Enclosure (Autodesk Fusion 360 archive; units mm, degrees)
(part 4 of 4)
sketch "Sketch57" plane through (0, 0, 0) normal (0, 0, -1) x axis (1, 0, 0)
  line L1 (10, -322.58) -> (10, -25)
  line L2 (232.58, -337.58) -> (25, -337.58)
  line L3 (247.58, -25) -> (247.58, -322.58)
  line L4 (25, -10) -> (232.58, -10)
  line L5 (103.7748, -244.2781) -> (91.8964, -251.7084)
  line L6 (108.0018, -231.1432) -> (108.0018, -236.648)
  line L7 (94.9373, -218.4422) -> (104.1813, -224.2382)
  line L8 (79.1901, -174.7773) -> (91.3374, -213.7689)
  line L9 (220.4778, -140.1755) -> (203.5713, -117.753)
  curve K1 (217.8042, -176.4831) -> (220.4778, -140.1755)
  line L10 (234.7917, -277.58) -> (234.7917, -212.7928)
  line L11 (94.639, -289.58) -> (222.7917, -289.58)
  line L12 (88.139, -258.4907) -> (88.139, -283.08)
  line L13 (158.8675, -75.8822) -> (158.8675, -124.8822)
  line L14 (102.3675, -68.3822) -> (151.3675, -68.3822)
  line L15 (94.8675, -124.8822) -> (94.8675, -75.8822)
  line L16 (151.3675, -132.3822) -> (102.3675, -132.3822)
  line L17 (184.5018, -268.1648) -> (135.5018, -268.1648)
  line L18 (192.0018, -211.6648) -> (192.0018, -260.6648)
  line L19 (135.5018, -204.1648) -> (184.5018, -204.1648)
  line L20 (128.0018, -260.6648) -> (128.0018, -211.6648)
  arc A1 centre (25, -25) radius 15 clockwise from (10, -25) to (25, -10)
  arc A2 centre (25, -322.58) radius 15 clockwise from (25, -337.58) to (10, -322.58)
  arc A3 centre (232.58, -322.58) radius 15 clockwise from (247.58, -322.58) to (232.58, -337.58)
  arc A4 centre (232.58, -25) radius 15 clockwise from (232.58, -10) to (247.58, -25)
  arc A5 centre (96.139, -258.4907) radius 8 clockwise from (88.139, -258.4907) to (91.8964, -251.7084)
  arc A6 centre (99.0018, -236.648) radius 9 clockwise from (108.0018, -236.648) to (103.7748, -244.2781)
  arc A7 centre (99.8518, -231.1432) radius 8.15 clockwise from (104.1813, -224.2382) to (108.0018, -231.1432)
  arc A8 centre (99.4527, -211.2407) radius 8.5 clockwise from (94.9373, -218.4422) to (91.3374, -213.7689)
  arc A9 centre (127.0824, -115.0779) radius 76.5356 clockwise from (79.1901, -174.7773) to (203.5713, -117.753)
  arc A10 centre (225.6505, -186.2784) radius 12.5504 clockwise from (223.1642, -198.5801) to (217.8042, -176.4831)
  arc A11 centre (220.2917, -212.7928) radius 14.5 clockwise from (223.1642, -198.5801) to (234.7917, -212.7928)
  arc A12 centre (222.7917, -277.58) radius 12 clockwise from (234.7917, -277.58) to (222.7917, -289.58)
  arc A13 centre (94.639, -283.08) radius 6.5 clockwise from (94.639, -289.58) to (88.139, -283.08)
  circle C1 centre (96.79, -233.79) radius 3
  circle C2 centre (88.5825, -41.4103) radius 4
  circle C3 centre (224.492, -186.2784) radius 3
  circle C4 centre (232.58, -322.58) radius 3
  circle C5 centre (237.58, -173.79) radius 3
  circle C6 centre (25, -25) radius 3
  circle C7 centre (25, -322.58) radius 3
  circle C8 centre (232.58, -25) radius 3
  circle C9 centre (20, -173.79) radius 3
  circle C10 centre (100.9647, -87.9081) radius 1.375
  circle C11 centre (100.9647, -112.8564) radius 1.375
  circle C12 centre (106.9491, -88.8821) radius 1.5
  circle C13 centre (154.3403, -108.8564) radius 1.375
  circle C14 centre (106.9489, -111.8821) radius 1.5
  circle C15 centre (119.001, -121.9951) radius 1.5
  circle C16 centre (150.622, -84.1868) radius 1.375
  circle C17 centre (112.0836, -82.7631) radius 1.5
  circle C18 centre (137.3711, -127.1448) radius 1.375
  circle C19 centre (149.5182, -96.3884) radius 1.5
  circle C20 centre (104.217, -104.376) radius 1.5
  circle C21 centre (105.7923, -80.8273) radius 1.375
  circle C22 centre (146.7861, -111.8823) radius 1.5
  circle C23 centre (129.0161, -129.0518) radius 1.375
  circle C24 centre (142.1417, -92.3657) radius 1.625
  circle C25 centre (137.3711, -73.6196) radius 1.375
  circle C26 centre (105.7923, -119.9372) radius 1.375
  circle C27 centre (98.4387, -96.0973) radius 1.375
  circle C28 centre (120.4701, -72.353) radius 1.375
  circle C29 centre (122.2157, -103.762) radius 1.875
  circle C30 centre (136.6667, -114.5787) radius 1.625
  circle C31 centre (128.6444, -94.9136) radius 1.875
  circle C32 centre (134.2595, -109.1918) radius 1.75
  circle C33 centre (144.1176, -100.3822) radius 1.625
  circle C34 centre (142.1417, -108.3987) radius 1.625
  circle C35 centre (120.7507, -84.2532) radius 1.625
  circle C36 centre (126.8676, -100.3822) radius 2
  circle C37 centre (120.7507, -116.5113) radius 1.625
  circle C38 centre (113.9558, -111.8211) radius 1.625
  circle C39 centre (116.9084, -94.6321) radius 1.75
  circle C40 centre (128.9468, -117.5065) radius 1.625
  circle C41 centre (126.8675, -111.8822) radius 1.75
  circle C42 centre (132.6176, -100.3822) radius 1.875
  circle C43 centre (115.5423, -102.379) radius 1.75
  circle C44 centre (130.8009, -89.5758) radius 1.75
  circle C45 centre (113.9558, -88.9434) radius 1.625
  circle C46 centre (155.6176, -100.3822) radius 1.375
  arc A14 centre (151.3675, -124.8822) radius 7.5 clockwise from (158.8675, -124.8822) to (151.3675, -132.3822)
  arc A15 centre (151.3675, -75.8822) radius 7.5 clockwise from (151.3675, -68.3822) to (158.8675, -75.8822)
  arc A16 centre (102.3675, -75.8822) radius 7.5 clockwise from (94.8675, -75.8822) to (102.3675, -68.3822)
  arc A17 centre (102.3675, -124.8822) radius 7.5 clockwise from (102.3675, -132.3822) to (94.8675, -124.8822)
  circle C47 centre (136.8269, -94.6323) radius 1.75
  circle C48 centre (138.1929, -102.3793) radius 1.75
  circle C49 centre (128.6444, -105.8508) radius 1.875
  circle C50 centre (119.4754, -109.1916) radius 1.75
  circle C51 centre (122.2157, -97.0025) radius 1.875
  circle C52 centre (136.6667, -86.1858) radius 1.625
  circle C53 centre (110.1188, -104.5104) radius 1.625
  circle C54 centre (128.9468, -83.258) radius 1.625
  circle C55 centre (122.9345, -89.5757) radius 1.75
  circle C56 centre (126.8675, -123.3822) radius 1.5
  circle C57 centre (110.1188, -96.254) radius 1.625
  circle C58 centre (144.7929, -122.8599) radius 1.375
  circle C59 centre (146.7862, -88.8823) radius 1.5
  circle C60 centre (126.8677, -77.3822) radius 1.5
  circle C61 centre (129.0161, -71.7126) radius 1.375
  circle C62 centre (144.7929, -77.9046) radius 1.375
  circle C63 centre (120.4701, -128.4114) radius 1.375
  circle C64 centre (154.3403, -91.908) radius 1.375
  circle C65 centre (134.7342, -78.7693) radius 1.5
  circle C66 centre (150.622, -116.5777) radius 1.375
  circle C67 centre (141.6518, -82.7633) radius 1.5
  circle C68 centre (149.5181, -104.3763) radius 1.5
  circle C69 centre (119.0012, -78.7692) radius 1.5
  circle C70 centre (112.4926, -75.484) radius 1.375
  circle C71 centre (141.6516, -118.0013) radius 1.5
  circle C72 centre (112.4926, -125.2805) radius 1.375
  circle C73 centre (104.217, -96.3882) radius 1.5
  circle C74 centre (134.7339, -121.9952) radius 1.5
  circle C75 centre (98.4387, -104.6672) radius 1.375
  circle C76 centre (112.0834, -118.0012) radius 1.5
  circle C77 centre (172.476, -210.2621) radius 1.375
  circle C78 centre (147.5277, -210.2621) radius 1.375
  circle C79 centre (171.502, -216.2464) radius 1.5
  circle C80 centre (151.5276, -263.6376) radius 1.375
  circle C81 centre (148.502, -216.2463) radius 1.5
  circle C82 centre (138.389, -228.2983) radius 1.5
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offset_faces "OffsetFaces1" distance 0.75 (= "acr_kerf")
step "Arrange11" AngleFromX 0 Priority 500 AngleFromX 0 Priority 500 AngleFromX 0 Priority 500 originOffsetX 0 originOffsetY 0 envelopeLength 270 envelopeWidth 400 envelopeSpacing 0 grainDirection 0 objectSpacing 20 frameWidth 10 placementClearance 0
sketch "Sketch58" plane through (0, 0, 2) normal (0, 0, 1) x axis (-1, 0, 0)
  line L1 (-10, -25.75) -> (-10, -323.33)
  line L2 (-233.33, -10) -> (-25.75, -10)
  line L3 (-249.08, -323.33) -> (-249.08, -25.75)
  line L4 (-25.75, -339.08) -> (-233.33, -339.08)
  line L5 (-104.5248, -104.0519) -> (-92.6464, -96.6216)
  line L6 (-108.7518, -117.1868) -> (-108.7518, -111.682)
  line L7 (-95.6873, -129.8877) -> (-104.9313, -124.0918)
  line L8 (-79.9401, -173.5527) -> (-92.0874, -134.561)
  line L9 (-221.2278, -208.1545) -> (-204.3213, -230.577)
  curve K1 (-218.5542, -171.8469) -> (-221.2278, -208.1545)
  line L10 (-235.5417, -70.75) -> (-235.5417, -135.5372)
  line L11 (-95.389, -58.75) -> (-223.5417, -58.75)
  line L12 (-88.889, -89.8392) -> (-88.889, -65.25)
  line L13 (-166.8314, -268.6862) -> (-166.8314, -219.6862)
  line L14 (-109.5814, -276.9362) -> (-158.5814, -276.9362)
  line L15 (-101.3314, -219.6862) -> (-101.3314, -268.6862)
  line L16 (-158.5814, -211.4362) -> (-109.5814, -211.4362)
  line L17 (-137.0019, -145.905) -> (-186.0019, -145.905)
  line L18 (-128.7519, -88.655) -> (-128.7519, -137.655)
  line L19 (-186.0019, -80.405) -> (-137.0019, -80.405)
  line L20 (-194.2519, -137.655) -> (-194.2519, -88.655)
  arc A1 centre (-25.75, -323.33) radius 15.75 clockwise from (-10, -323.33) to (-25.75, -339.08)
  arc A2 centre (-25.75, -25.75) radius 15.75 clockwise from (-25.75, -10) to (-10, -25.75)
  arc A3 centre (-233.33, -25.75) radius 15.75 clockwise from (-249.08, -25.75) to (-233.33, -10)
  arc A4 centre (-233.33, -323.33) radius 15.75 clockwise from (-233.33, -339.08) to (-249.08, -323.33)
  arc A5 centre (-96.889, -89.8392) radius 8 clockwise from (-88.889, -89.8392) to (-92.6464, -96.6216)
  arc A6 centre (-99.7518, -111.682) radius 9 clockwise from (-108.7518, -111.682) to (-104.5248, -104.0519)
  arc A7 centre (-100.6018, -117.1868) radius 8.15 clockwise from (-104.9313, -124.0918) to (-108.7518, -117.1868)
  arc A8 centre (-100.2027, -137.0892) radius 8.5 clockwise from (-95.6873, -129.8877) to (-92.0874, -134.561)
  arc A9 centre (-127.8324, -233.2521) radius 76.5356 clockwise from (-79.9401, -173.5527) to (-204.3213, -230.577)
  arc A10 centre (-226.4005, -162.0515) radius 12.5504 clockwise from (-223.9142, -149.7498) to (-218.5542, -171.8469)
  arc A11 centre (-221.0417, -135.5372) radius 14.5 clockwise from (-223.9142, -149.7498) to (-235.5417, -135.5372)
  arc A12 centre (-223.5417, -70.75) radius 12 clockwise from (-235.5417, -70.75) to (-223.5417, -58.75)
  arc A13 centre (-95.389, -65.25) radius 6.5 clockwise from (-95.389, -58.75) to (-88.889, -65.25)
  circle C1 centre (-97.54, -114.54) radius 3
  circle C2 centre (-89.3325, -306.9197) radius 4
  circle C3 centre (-225.242, -162.0515) radius 3
  circle C4 centre (-233.33, -25.75) radius 3
  circle C5 centre (-238.33, -174.54) radius 3
  circle C6 centre (-25.75, -323.33) radius 3
  circle C7 centre (-25.75, -25.75) radius 3
  circle C8 centre (-233.33, -323.33) radius 3
  circle C9 centre (-20.75, -174.54) radius 3
  circle C10 centre (-121.6072, -270.0889) radius 1.375
  circle C11 centre (-146.5555, -270.0889) radius 1.375
  circle C12 centre (-122.5812, -264.1046) radius 1.5
  circle C13 centre (-142.5556, -216.7133) radius 1.375
  circle C14 centre (-145.5812, -264.1047) radius 1.5
  circle C15 centre (-155.6942, -252.0527) radius 1.5
  circle C16 centre (-117.8859, -220.4317) radius 1.375
  circle C17 centre (-116.4622, -258.9701) radius 1.5
  circle C18 centre (-160.844, -233.6825) radius 1.375
  circle C19 centre (-130.0876, -221.5355) radius 1.5
  circle C20 centre (-138.0751, -266.8367) radius 1.5
  circle C21 centre (-114.5264, -265.2613) radius 1.375
  circle C22 centre (-145.5815, -224.2675) radius 1.5
  circle C23 centre (-162.751, -242.0376) radius 1.375
  circle C24 centre (-126.0649, -228.9119) radius 1.625
  circle C25 centre (-107.3187, -233.6825) radius 1.375
  circle C26 centre (-153.6363, -265.2613) radius 1.375
  circle C27 centre (-129.7964, -272.6149) radius 1.375
  circle C28 centre (-106.0522, -250.5835) radius 1.375
  circle C29 centre (-137.4611, -248.8379) radius 1.875
  circle C30 centre (-148.2778, -234.3869) radius 1.625
  circle C31 centre (-128.6128, -242.4092) radius 1.875
  circle C32 centre (-142.8909, -236.7941) radius 1.75
  circle C33 centre (-134.0814, -226.9361) radius 1.625
  circle C34 centre (-142.0978, -228.9119) radius 1.625
  circle C35 centre (-117.9523, -250.303) radius 1.625
  circle C36 centre (-134.0814, -244.1861) radius 2
  circle C37 centre (-150.2104, -250.303) radius 1.625
  circle C38 centre (-145.5202, -257.0979) radius 1.625
  circle C39 centre (-128.3312, -254.1453) radius 1.75
  circle C40 centre (-151.2056, -242.1068) radius 1.625
  circle C41 centre (-145.5814, -244.1862) radius 1.75
  circle C42 centre (-134.0814, -238.4361) radius 1.875
  circle C43 centre (-136.0782, -255.5114) radius 1.75
  circle C44 centre (-123.2749, -240.2527) radius 1.75
  circle C45 centre (-122.6425, -257.0979) radius 1.625
  circle C46 centre (-134.0814, -215.4361) radius 1.375
  arc A14 centre (-158.5814, -219.6862) radius 8.25 clockwise from (-166.8314, -219.6862) to (-158.5814, -211.4362)
  arc A15 centre (-158.5814, -268.6862) radius 8.25 clockwise from (-158.5814, -276.9362) to (-166.8314, -268.6862)
  arc A16 centre (-109.5814, -268.6862) radius 8.25 clockwise from (-101.3314, -268.6862) to (-109.5814, -276.9362)
  arc A17 centre (-109.5814, -219.6862) radius 8.25 clockwise from (-109.5814, -211.4362) to (-101.3314, -219.6862)
  circle C47 centre (-128.3315, -234.2267) radius 1.75
  circle C48 centre (-136.0784, -232.8608) radius 1.75
  circle C49 centre (-139.5499, -242.4092) radius 1.875
  circle C50 centre (-142.8908, -251.5782) radius 1.75
  circle C51 centre (-130.7016, -248.8379) radius 1.875
  circle C52 centre (-119.8849, -234.3869) radius 1.625
  circle C53 centre (-138.2095, -260.9348) radius 1.625
  circle C54 centre (-116.9571, -242.1068) radius 1.625
  circle C55 centre (-123.2748, -248.1192) radius 1.75
  circle C56 centre (-157.0814, -244.1862) radius 1.5
  circle C57 centre (-129.9532, -260.9348) radius 1.625
  circle C58 centre (-156.559, -226.2607) radius 1.375
  circle C59 centre (-122.5815, -224.2674) radius 1.5
  circle C60 centre (-111.0814, -244.1859) radius 1.5
  circle C61 centre (-105.4117, -242.0376) radius 1.375
  circle C62 centre (-111.6037, -226.2607) radius 1.375
  circle C63 centre (-162.1105, -250.5835) radius 1.375
  circle C64 centre (-125.6071, -216.7133) radius 1.375
  circle C65 centre (-112.4685, -236.3195) radius 1.5
  circle C66 centre (-150.2768, -220.4317) radius 1.375
  circle C67 centre (-116.4624, -229.4018) radius 1.5
  circle C68 centre (-138.0754, -221.5355) radius 1.5
  circle C69 centre (-112.4684, -252.0524) radius 1.5
  circle C70 centre (-109.1831, -258.5611) radius 1.375
  circle C71 centre (-151.7005, -229.402) radius 1.5
  circle C72 centre (-158.9796, -258.5611) radius 1.375
  circle C73 centre (-130.0873, -266.8366) radius 1.5
  circle C74 centre (-155.6943, -236.3197) radius 1.5
  circle C75 centre (-138.3663, -272.6149) radius 1.375
  circle C76 centre (-151.7003, -258.9703) radius 1.5
  circle C77 centre (-135.5992, -100.6808) radius 1.375
  circle C78 centre (-135.5992, -125.6291) radius 1.375
  circle C79 centre (-141.5835, -101.6549) radius 1.5
  circle C80 centre (-188.9747, -121.6292) radius 1.375
  circle C81 centre (-141.5834, -124.6549) radius 1.5
  circle C82 centre (-153.6354, -134.7679) radius 1.5
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component_from_bodies "Body->Comp23"
component_from_bodies "Body->Comp24"
component_from_bodies "Body->Comp25"
offset_faces "OffsetFaces1" distance -2.5
sketch "Sketch59" plane through (0, -174.4464, 63.4933) normal (0, -0.9397, 0.342) x axis (1, 0, 0)
  line L1 (16, -22.9002) -> (16, 15.0998)
  line L2 (-45, -22.9002) -> (16, -22.9002)
  line L3 (-48, 12.0998) -> (-48, -19.9002)
  line L4 (16, 15.0998) -> (-45, 15.0998)
  line L5 (50, 12.0998) -> (50, -19.9002)
  line L6 (-45, 17.0998) -> (45, 17.0998)
  line L7 (-50, -19.9002) -> (-50, 12.0998)
  line L8 (45, -24.9002) -> (-45, -24.9002)
  arc A1 centre (-45, -19.9002) radius 3 clockwise from (-45, -22.9002) to (-48, -19.9002)
  arc A2 centre (-45, 12.0998) radius 3 clockwise from (-48, 12.0998) to (-45, 15.0998)
  arc A3 centre (45, -19.9002) radius 5 clockwise from (50, -19.9002) to (45, -24.9002)
  arc A4 centre (45, 12.0998) radius 5 clockwise from (45, 17.0998) to (50, 12.0998)
  arc A5 centre (-45, 12.0998) radius 5 clockwise from (-50, 12.0998) to (-45, 17.0998)
  arc A6 centre (-45, -19.9002) radius 5 clockwise from (-45, -24.9002) to (-50, -19.9002)
  circle C1 centre (31.25, -3.9002) radius 12.5
  circle C2 centre (31.25, -3.9002) radius 12.5
  circle C3 centre (31.25, -3.9002) radius 11.75
  dimension "d434" = -0.75
extrude "Extrude39" new body sketch "Sketch59" profile of C3 along normal blind 7.5 bodies "KNOB"
fillet "Fillet8" radius 2.5
sketch "Sketch60" plane through (0, -181.4941, 66.0584) normal (0, -0.9397, 0.342) x axis (1, 0, 0)
  circle C1 centre (31.25, -3.9002) radius 9.25
extrude "Extrude40" cut sketch "Sketch60" against normal blind 1
sketch "Sketch61" plane through (0, -180.5544, 65.7164) normal (0, -0.9397, 0.342) x axis (1, 0, 0)
  circle C1 centre (31.25, -3.9002) radius 9.25
  point P2 (31.25, -3.9002)
  point P3 (31.25, -3.9002)
  coincident P2 P3
loft "Loft1" sketch "Sketch60"
extrude "Extrude41" add of existing geometry blind 1
combine "Combine1"
sketch "Sketch62" plane through (0, -174.4464, 63.4933) normal (0, 0.9397, -0.342) x axis (-1, 0, 0)
  circle C1 centre (-31.25, -3.9002) radius 11.75
  circle C2 centre (-31.25, -3.9002) radius 2.8625
  concentric C1 C2
  dimension "d444" diameter C2 = 5.725
extrude "Extrude42" cut sketch "Sketch62" profile of C2 against normal blind 5
extrude "Extrude43" add of existing geometry blind 5
offset_faces "OffsetFaces1" bodies "L1_2"
offset_faces "OffsetFaces5"
component_from_bodies "Body->Comp26"
offset_faces "OffsetFaces1" distance -4
offset_faces "OffsetFaces2" distance 2.5
sketch "Sketch67" plane through (0, -174.4464, 63.4933) normal (0, -0.9397, 0.342) x axis (1, 0, 0)
  line L1 (-48, 12.0998) -> (-48, -19.9002)
  line L2 (16, 15.0998) -> (-45, 15.0998)
  line L3 (16, -22.9002) -> (16, 15.0998)
  line L4 (-45, -22.9002) -> (16, -22.9002)
  line L5 (-50, -19.9002) -> (-50, 12.0998)
  line L6 (45, -24.9002) -> (-45, -24.9002)
  line L7 (50, 12.0998) -> (50, -19.9002)
  line L8 (-45, 17.0998) -> (45, 17.0998)
  line L9 (31.25, -24.9002) -> (31.25, 17.0998)
  arc A1 centre (-45, 12.0998) radius 3 clockwise from (-48, 12.0998) to (-45, 15.0998)
  arc A2 centre (-45, -19.9002) radius 3 clockwise from (-45, -22.9002) to (-48, -19.9002)
  arc A3 centre (-45, -19.9002) radius 5 clockwise from (-45, -24.9002) to (-50, -19.9002)
  arc A4 centre (45, -19.9002) radius 5 clockwise from (50, -19.9002) to (45, -24.9002)
  arc A5 centre (45, 12.0998) radius 5 clockwise from (45, 17.0998) to (50, 12.0998)
  arc A6 centre (-45, 12.0998) radius 5 clockwise from (-50, 12.0998) to (-45, 17.0998)
  circle C1 centre (31.25, -3.9002) radius 12.5
  circle C2 centre (31.25, -3.9002) radius 12.5
  circle C3 centre (31.25, -2.4002) radius 12.5
  point P22 (31.25, 17.0998)
  point P23 (31.25, -24.9002)
  point P20 (31.25, -3.9002)
  point P24 (31.25, -2.4002)
  point P25 (31.25, -2.4002)
  coincident L8 P22
  coincident L6 P23
  perpendicular L6 L9
  coincident P20 L9
  coincident L9 P24
  coincident P24 P25
  dimension "d479" distance L6 P24 = 22.5 (= "16.5 mm + 6 mm")
  dimension "d480" diameter C3 = 25
extrude "Extrude1" add sketch "Sketch67" profile of C1 C2 C3 against normal blind 5
extrude "Extrude2" cut sketch "Sketch67" profile of C1 C2 C3 against normal blind 5
extrude "Extrude1" add of existing geometry blind 2
offset_faces "OffsetFaces2"
offset_faces "OffsetFaces3"
sketch "Sketch68" plane through (0, -174.4464, 63.4933) normal (0, -0.9397, 0.342) x axis (1, 0, 0)
  line L1 (-48, 12.0998) -> (-48, -19.9002)
  line L2 (16, 15.0998) -> (-45, 15.0998)
  line L3 (16, -22.9002) -> (16, 15.0998)
  line L4 (-45, -22.9002) -> (16, -22.9002)
  line L5 (-50, -19.9002) -> (-50, 12.0998)
  line L6 (45, -24.9002) -> (-45, -24.9002)
  line L7 (50, 12.0998) -> (50, -19.9002)
  line L8 (-45, 17.0998) -> (45, 17.0998)
  line L9 (16, -22.9002) -> (-45, -22.9002)
  line L10 (16, -21.4002) -> (16, -22.9002)
  line L11 (-41.5, -21.4002) -> (16, -21.4002)
  line L12 (-41.5, -13.9002) -> (-41.5, -21.4002)
  line L13 (-46.5, -10.4002) -> (-45, -10.4002)
  line L14 (-46.5, 2.5998) -> (-46.5, -10.4002)
  line L15 (-45, 2.5998) -> (-46.5, 2.5998)
  line L16 (-41.5, 13.5998) -> (-41.5, 6.0998)
  line L17 (16, 13.5998) -> (-41.5, 13.5998)
  line L18 (16, 15.0998) -> (16, 13.5998)
  line L19 (-45, 15.0998) -> (16, 15.0998)
  line L20 (-48, -19.9002) -> (-48, 12.0998)
  line L21 (16, -22.9002) -> (16, 15.0998)
  circle C1 centre (31.25, -2.4002) radius 12.5
  arc A1 centre (-45, 12.0998) radius 3 clockwise from (-48, 12.0998) to (-45, 15.0998)
  arc A2 centre (-45, -19.9002) radius 3 clockwise from (-45, -22.9002) to (-48, -19.9002)
  arc A3 centre (-45, -19.9002) radius 5 clockwise from (-45, -24.9002) to (-50, -19.9002)
  arc A4 centre (45, -19.9002) radius 5 clockwise from (50, -19.9002) to (45, -24.9002)
  arc A5 centre (45, 12.0998) radius 5 clockwise from (45, 17.0998) to (50, 12.0998)
  arc A6 centre (-45, 12.0998) radius 5 clockwise from (-50, 12.0998) to (-45, 17.0998)
  arc A7 centre (-45, -19.9002) radius 3 clockwise from (-45, -22.9002) to (-48, -19.9002)
  arc A8 centre (-45, -13.9002) radius 3.5 clockwise from (-45, -10.4002) to (-41.5, -13.9002)
  arc A9 centre (-45, 6.0998) radius 3.5 clockwise from (-41.5, 6.0998) to (-45, 2.5998)
  arc A10 centre (-45, 12.0998) radius 3 clockwise from (-48, 12.0998) to (-45, 15.0998)
  circle C2 centre (-45, 6.0998) radius 1.5
  circle C3 centre (-45, -13.9002) radius 1.5
offset_faces "OffsetFaces2"
extrude "Extrude4" add of existing geometry blind 3.5 (= "6 mm - 2.5 mm")
offset_faces "OffsetFaces3"
offset_faces "OffsetFaces4" distance -1
chamfer "Chamfer1" distance 4
chamfer "Chamfer1" distance 0.5
sketch "Sketch69" plane through (0, 0, 100.89) normal (0, 0, 1) x axis (-1, 0, 0)
  line L1 (-148.79, 119.54) -> (148.79, 119.54)
  line L2 (-164.54, -103.79) -> (-164.54, 103.79)
  line L3 (148.79, -119.54) -> (-148.79, -119.54)
  line L4 (164.54, 103.79) -> (164.54, -103.79)
  line L5 (-70.4881, 25.0153) -> (-77.9184, 36.8936)
  line L6 (-57.3532, 20.7882) -> (-62.858, 20.7882)
  line L7 (-44.6522, 33.8527) -> (-50.4482, 24.6087)
  line L8 (-0.9873, 49.5999) -> (-39.979, 37.4526)
  line L9 (33.6145, -91.6878) -> (56.037, -74.7812)
  curve K1 (-2.6931, -89.0142) -> (33.6145, -91.6878)
  line L10 (-103.79, -106.0016) -> (-39.0028, -106.0016)
  line L11 (-115.79, 34.151) -> (-115.79, -94.0016)
  line L12 (-84.7008, 40.651) -> (-109.29, 40.651)
  arc A1 centre (148.79, 103.79) radius 15.75 clockwise from (148.79, 119.54) to (164.54, 103.79)
  arc A2 centre (-148.79, 103.79) radius 15.75 clockwise from (-164.54, 103.79) to (-148.79, 119.54)
  arc A3 centre (-148.79, -103.79) radius 15.75 clockwise from (-148.79, -119.54) to (-164.54, -103.79)
  arc A4 centre (148.79, -103.79) radius 15.75 clockwise from (164.54, -103.79) to (148.79, -119.54)
  arc A5 centre (-84.7008, 32.651) radius 8 clockwise from (-84.7008, 40.651) to (-77.9184, 36.8936)
  arc A6 centre (-62.858, 29.7882) radius 9 clockwise from (-62.858, 20.7882) to (-70.4881, 25.0153)
  arc A7 centre (-57.3532, 28.9382) radius 8.15 clockwise from (-50.4482, 24.6087) to (-57.3532, 20.7882)
  arc A8 centre (-37.4507, 29.3373) radius 8.5 clockwise from (-44.6522, 33.8527) to (-39.979, 37.4526)
  arc A9 centre (58.7121, 1.7076) radius 76.5356 clockwise from (-0.9873, 49.5999) to (56.037, -74.7812)
  arc A10 centre (-12.4884, -96.8605) radius 12.5504 clockwise from (-12.4884, -96.8605) to (-24.7901, -94.3742)
  arc A11 centre (-39.0028, -91.5016) radius 14.5 clockwise from (-24.7901, -94.3742) to (-39.0028, -106.0016)
  arc A12 centre (-103.79, -94.0016) radius 12 clockwise from (-103.79, -106.0016) to (-115.79, -94.0016)
  arc A13 centre (-109.29, 34.151) radius 6.5 clockwise from (-115.79, 34.151) to (-109.29, 40.651)
  circle C1 centre (-60, 32) radius 3
  circle C2 centre (132.3797, 40.2075) radius 4
  circle C3 centre (-12.4884, -95.702) radius 3
  circle C4 centre (-148.79, -103.79) radius 3
  circle C5 centre (0, -108.79) radius 3
  circle C6 centre (148.79, 103.79) radius 3
  circle C7 centre (-148.79, 103.79) radius 3
  circle C8 centre (148.79, -103.79) radius 3
  circle C9 centre (0, 108.79) radius 3
  circle C10 centre (-60, 32) radius 3
  circle C11 centre (-12.4884, -95.702) radius 3
  circle C12 centre (132.3797, 40.2075) radius 4
  circle C13 centre (-60, 32) radius 5.25
  circle C14 centre (-12.4884, -95.702) radius 5.25
  circle C15 centre (132.2263, 39.8878) radius 5.25
  concentric C10 C13
  concentric C11 C14
  dimension "d500" diameter C13 = 10.5
  dimension "d501" diameter C14 = 10.5
  dimension "d502" diameter C15 = 10.5
extrude "Extrude3" cut sketch "Sketch69" profile of C1 C2 C3 C10 C11 C12 C13 C14 C15 against normal blind 2
offset_faces "OffsetFaces2" distance 0.75 (= "acr_kerf")
copy_paste_bodies "CopyPasteBodies9"
component_from_bodies "Body->Comp27"
step "Arrange12" AngleFromX 0 Priority 500 originOffsetX 0 originOffsetY 0 envelopeLength 270 envelopeWidth 400 envelopeSpacing 0 grainDirection 0 objectSpacing 40 frameWidth 10 placementClearance 0
sketch "Sketch71" plane through (0, 0, 2) normal (0, 0, 1) x axis (-1, 0, 0)
  line L1 (-104.5248, -104.0519) -> (-92.6464, -96.6216)
  line L2 (-108.7518, -117.1868) -> (-108.7518, -111.682)
  line L3 (-95.6873, -129.8877) -> (-104.9313, -124.0918)
  line L4 (-79.9401, -173.5527) -> (-92.0874, -134.561)
  line L5 (-221.2278, -208.1545) -> (-204.3213, -230.577)
  curve K1 (-218.5542, -171.8469) -> (-221.2278, -208.1545)
  line L6 (-235.5417, -70.75) -> (-235.5417, -135.5372)
  line L7 (-95.389, -58.75) -> (-223.5417, -58.75)
  line L8 (-88.889, -89.8392) -> (-88.889, -65.25)
  line L9 (-10, -25.75) -> (-10, -323.33)
  line L10 (-233.33, -10) -> (-25.75, -10)
  line L11 (-249.08, -323.33) -> (-249.08, -25.75)
  line L12 (-25.75, -339.08) -> (-233.33, -339.08)
  line L13 (-10, -25.75) -> (-10, -323.33)
  line L14 (-25.75, -339.08) -> (-233.33, -339.08)
  line L15 (-249.08, -323.33) -> (-249.08, -25.75)
  line L16 (-233.33, -10) -> (-25.75, -10)
  circle C1 centre (-20.75, -174.54) radius 3
  circle C2 centre (-233.33, -323.33) radius 3
  circle C3 centre (-25.75, -25.75) radius 3
  circle C4 centre (-25.75, -323.33) radius 3
  circle C5 centre (-238.33, -174.54) radius 3
  circle C6 centre (-233.33, -25.75) radius 3
  arc A1 centre (-96.889, -89.8392) radius 8 clockwise from (-88.889, -89.8392) to (-92.6464, -96.6216)
  arc A2 centre (-99.7518, -111.682) radius 9 clockwise from (-108.7518, -111.682) to (-104.5248, -104.0519)
  arc A3 centre (-100.6018, -117.1868) radius 8.15 clockwise from (-104.9313, -124.0918) to (-108.7518, -117.1868)
  arc A4 centre (-100.2027, -137.0892) radius 8.5 clockwise from (-95.6873, -129.8877) to (-92.0874, -134.561)
  arc A5 centre (-127.8324, -233.2521) radius 76.5356 clockwise from (-79.9401, -173.5527) to (-204.3213, -230.577)
  arc A6 centre (-226.4005, -162.0515) radius 12.5504 clockwise from (-223.9142, -149.7498) to (-218.5542, -171.8469)
  arc A7 centre (-221.0417, -135.5372) radius 14.5 clockwise from (-223.9142, -149.7498) to (-235.5417, -135.5372)
  arc A8 centre (-223.5417, -70.75) radius 12 clockwise from (-235.5417, -70.75) to (-223.5417, -58.75)
  arc A9 centre (-95.389, -65.25) radius 6.5 clockwise from (-95.389, -58.75) to (-88.889, -65.25)
  arc A10 centre (-25.75, -323.33) radius 15.75 clockwise from (-10, -323.33) to (-25.75, -339.08)
  arc A11 centre (-25.75, -25.75) radius 15.75 clockwise from (-25.75, -10) to (-10, -25.75)
  arc A12 centre (-233.33, -25.75) radius 15.75 clockwise from (-249.08, -25.75) to (-233.33, -10)
  arc A13 centre (-233.33, -323.33) radius 15.75 clockwise from (-233.33, -339.08) to (-249.08, -323.33)
  circle C7 centre (-89.6522, -306.7663) radius 4.5
  circle C8 centre (-97.54, -114.54) radius 4.5
  circle C9 centre (-225.242, -162.0515) radius 4.5
  arc A14 centre (-25.75, -323.33) radius 15.75 clockwise from (-10, -323.33) to (-25.75, -339.08)
  arc A15 centre (-233.33, -323.33) radius 15.75 clockwise from (-233.33, -339.08) to (-249.08, -323.33)
  arc A16 centre (-233.33, -25.75) radius 15.75 clockwise from (-249.08, -25.75) to (-233.33, -10)
  arc A17 centre (-25.75, -25.75) radius 15.75 clockwise from (-25.75, -10) to (-10, -25.75)
  circle C10 centre (-225.242, -162.0515) radius 4.5
  circle C11 centre (-89.6522, -306.7663) radius 4.5
  circle C12 centre (-97.54, -114.54) radius 4.5
sketch "Sketch72" plane through (0, -174.4464, 63.4933) normal (0, -0.9397, 0.342) x axis (1, 0, 0)
  line L1 (-47.65, -19.9002) -> (-47.65, 12.0998)
  line L2 (12.15, -22.5502) -> (-45, -22.5502)
  line L3 (12.15, 14.7498) -> (12.15, -22.5502)
  line L4 (-45, 14.7498) -> (12.15, 14.7498)
  arc A1 centre (-45, 12.0998) radius 2.65 clockwise from (-47.65, 12.0998) to (-45, 14.7498)
  arc A2 centre (-45, -19.9002) radius 2.65 clockwise from (-45, -22.5502) to (-47.65, -19.9002)
offset_faces "OffsetFaces1" distance 0.55 (= "( 1.1 / 2 ) * 1 mm")
sketch "Sketch73" plane through (0, -174.4464, 63.4933) normal (0, -0.9397, 0.342) x axis (1, 0, 0)
  line L1 (-48.2, -19.9002) -> (-48.2, 12.0998)
  line L2 (12.7, -23.1002) -> (-45, -23.1002)
  line L3 (12.7, 15.2998) -> (12.7, -23.1002)
  line L4 (-45, 15.2998) -> (12.7, 15.2998)
  arc A1 centre (-45, 12.0998) radius 3.2 clockwise from (-48.2, 12.0998) to (-45, 15.2998)
  arc A2 centre (-45, -19.9002) radius 3.2 clockwise from (-45, -23.1002) to (-48.2, -19.9002)
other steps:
base_feature "Base Feature1" bodies "SPEAKER_1"
base_feature "Base Feature1" bodies "CASE"
base_feature "Base Feature1" bodies "WIRES"
base_feature "Base Feature1" bodies "CASE_FEED"
base_feature "Base Feature1" bodies "SCREEN"
base_feature "Base Feature1" bodies "KNOB"
offset_faces "OffsetFaces1" distance 0.75 (= "acr_kerf")
base_feature "Base Feature1" bodies "BOTTOM"
base_feature "Base Feature1" bodies "R1_2"
base_feature "Base Feature1" bodies "TOP"
base_feature "Base Feature1" bodies "ACRYLIC"
base_feature "Base Feature1" bodies "BACK"
base_feature "Base Feature1" bodies "FRONT"
base_feature "Base Feature1" bodies "L1_2"
base_feature "Base Feature1" bodies "L3"
base_feature "Base Feature1" bodies "L1"
base_feature "Base Feature1" bodies "L2"
base_feature "Base Feature1" bodies "R2"
base_feature "Base Feature1" bodies "R5"
base_feature "Base Feature1" bodies "L5"
base_feature "Base Feature1" bodies "R1"
base_feature "Base Feature1" bodies "R4"
base_feature "Base Feature1" bodies "L4"
base_feature "Base Feature1" bodies "R6"
base_feature "Base Feature1" bodies "L6"
base_feature "Base Feature1" bodies "L7"
base_feature "Base Feature1" bodies "R3"
base_feature "Base Feature1" bodies "R7"
base_feature "Base Feature1" bodies "L2", "R2"
base_feature "Base Feature2" bodies "L1_2", "R1_2"
base_feature "Base Feature3" bodies "R3", "L3"
base_feature "Base Feature4" bodies "R4", "L4"
base_feature "Base Feature5" bodies "R5", "L5"
base_feature "Base Feature6" bodies "R6", "L6"
base_feature "Base Feature8" bodies "R7", "L7"
base_feature "Base Feature9" bodies "SCREEN"
create_component "CreateComponent1"
reparent_decal "ReparentDecal1"
remove_body "RemoveBody1"
create_component "CreateComponent2"
reparent_decal "ReparentDecal2"
remove_body "RemoveBody2"
create_component "CreateComponent3"
reparent_decal "ReparentDecal3"
remove_body "RemoveBody3"
create_component "CreateComponent4"
reparent_decal "ReparentDecal4"
remove_body "RemoveBody4"
create_component "CreateComponent5"
reparent_decal "ReparentDecal5"
remove_body "RemoveBody5"
create_component "CreateComponent6"
reparent_decal "ReparentDecal6"
remove_body "RemoveBody6"
create_component "CreateComponent7"
reparent_decal "ReparentDecal7"
remove_body "RemoveBody7"
create_component "CreateComponent8"
reparent_decal "ReparentDecal8"
remove_body "RemoveBody8"
create_component "CreateComponent9"
reparent_decal "ReparentDecal9"
remove_body "RemoveBody9"
create_component "CreateComponent10"
reparent_decal "ReparentDecal10"
remove_body "RemoveBody10"
create_component "CreateComponent11"
reparent_decal "ReparentDecal11"
remove_body "RemoveBody11"
create_component "CreateComponent12"
reparent_decal "ReparentDecal12"
remove_body "RemoveBody12"
create_component "CreateComponent13"
reparent_decal "ReparentDecal13"
remove_body "RemoveBody13"
create_component "CreateComponent14"
reparent_decal "ReparentDecal14"
remove_body "RemoveBody14"
create_component "CreateComponent15"
reparent_decal "ReparentDecal15"
remove_body "RemoveBody15"
create_component "CreateComponent16"
reparent_decal "ReparentDecal16"
remove_body "RemoveBody16"
create_component "CreateComponent17"
reparent_decal "ReparentDecal17"
remove_body "RemoveBody17"
create_component "CreateComponent18"
reparent_decal "ReparentDecal18"
remove_body "RemoveBody18"
create_component "CreateComponent19"
reparent_decal "ReparentDecal19"
remove_body "RemoveBody19"
create_component "CreateComponent20"
reparent_decal "ReparentDecal20"
remove_body "RemoveBody20"
create_component "CreateComponent21"
reparent_decal "ReparentDecal21"
remove_body "RemoveBody21"
create_component "CreateComponent25"
create_component "CreateComponent1"
create_component "CreateComponent26"
create_component "CreateComponent1"
create_component "CreateComponent27"
reparent_decal "ReparentDecal22"
remove_body "RemoveBody22"
create_component "CreateComponent28"
create_component "CreateComponent1"
create_component "CreateComponent29"
create_component "CreateComponent1"
create_component "CreateComponent30"
create_component "CreateComponent1"
create_component "CreateComponent32"
create_component "CreateComponent1"
create_component "CreateComponent33"
create_component "CreateComponent1"
create_component "CreateComponent34"
reparent_decal "ReparentDecal23"
remove_body "RemoveBody23"
create_component "CreateComponent35"
reparent_decal "ReparentDecal24"
remove_body "RemoveBody24"
create_component "CreateComponent36"
reparent_decal "ReparentDecal25"
remove_body "RemoveBody25"
create_component "CreateComponent37"
reparent_decal "ReparentDecal26"
remove_body "RemoveBody26"
create_component "CreateComponent38"
reparent_decal "ReparentDecal27"
remove_body "RemoveBody27"
create_component "CreateComponent39"
create_component "CreateComponent1"
named bodies: "BOTTOM", "L1", "R1", "L2", "R2", "L1_2", "R1_2", "R3", "L3", "R4", "L4", "R5", "L5", "R6", "L6", "R7", "L7", "TOP", "ACRYLIC", "BACK", "FRONT", "CASE", "WIRES", "dogboneTool", "dogboneTool (1)", "CASE_FEED", "SPEAKER_1", "KNOB", "CASE (1)", "SCREEN"

design "IO_BOARD"
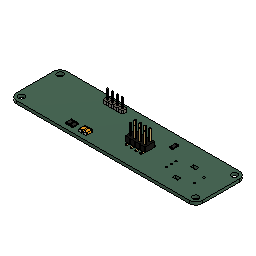
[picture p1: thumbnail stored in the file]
description: KiCad electronic assembly
part number: IO_BOARD 1
description: Part Number
part number: Ceramic
part number: Contacts
part number: Contacts (Mirror #1)
part number: Overcoat
part number: Resistor-1206
part number: IO_BOARD 1.2.1
part number: IO_BOARD 1.2.2
part number: IO_BOARD 1.2.3
part number: IO_BOARD 1.2.4
base_feature "Base Feature1"
base_feature "Base Feature1"
base_feature "Base Feature1"
base_feature "Base Feature1"
base_feature "Base Feature1"
base_feature "Base Feature1"
base_feature "Base Feature1"
base_feature "Base Feature1"
base_feature "Base Feature1"
base_feature "Base Feature1"
base_feature "Base Feature1"
base_feature "Base Feature1"
base_feature "Base Feature1"
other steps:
create_component "CreateComponent1"
create_component "CreateComponent1"
create_component "CreateComponent2"
create_component "CreateComponent3"
create_component "CreateComponent4"
create_component "CreateComponent2"
create_component "CreateComponent1"
create_component "CreateComponent2"
create_component "CreateComponent3"
create_component "CreateComponent4"
create_component "CreateComponent3"
create_component "CreateComponent1"
create_component "CreateComponent2"
create_component "CreateComponent3"
create_component "CreateComponent4"
create_component "CreateComponent5"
